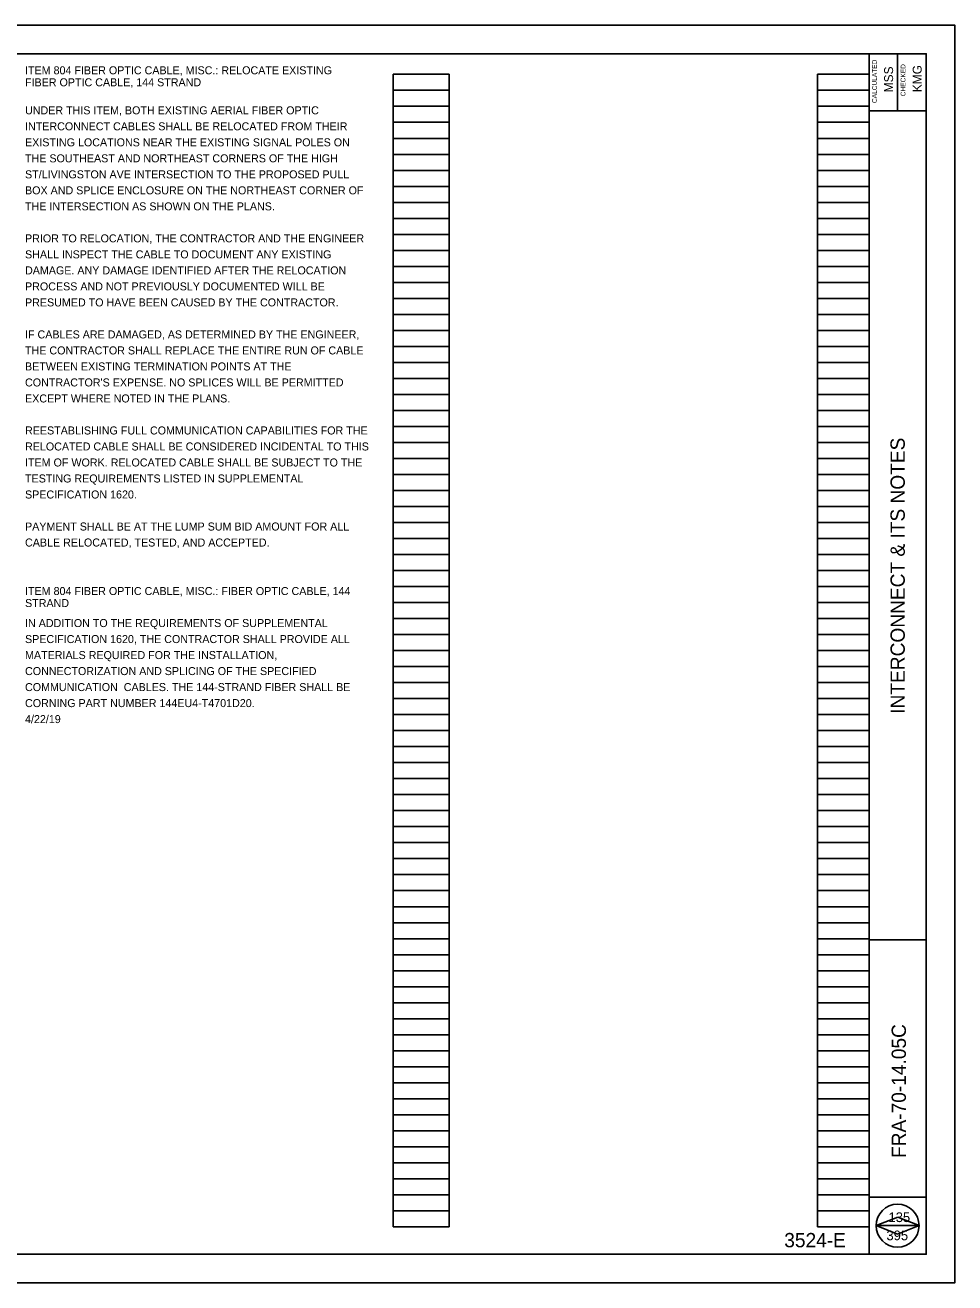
# Model space of a CAD drawing. Extents: x -39 to 75, y -25 to 14.
# Drawn here: x 17.24 to 33.49, y -7.51 to 14.49 of the extents above; entities that cross this region are included whole.
import ezdxf

# ---------------------------------------------------------------- set-up
doc = ezdxf.new("R2010")
doc.units = 0
for name, color, linetype in [('Level 63', 7, 'Continuous'), ('PF_P_Text', 7, 'Continuous'), ('SC_Scratch1', 7, 'Continuous'), ('SH_Cut_Line', 7, 'Continuous'), ('SH_Data', 7, 'Continuous'), ('SH_Text', 7, 'Continuous')]:
    doc.layers.add(name, color=color, linetype=linetype)

msp = doc.modelspace()

# ---------------------------------------------------------------- linework, layer by layer
at = {"layer": 'Level 63'}
msp.add_line((32.119, -6.508), (32.869, -6.508), dxfattribs=at)
msp.add_line((32.119, -6.508), (32.869, -6.508), dxfattribs=at)
msp.add_circle((32.494, -6.508), 0.375, dxfattribs=at)
at = {"layer": 'PF_P_Text'}
for p, q in [((31.994, -7.008), (31.994, 13.992)), ((32.494, 13.992), (32.494, 12.992)), ((31.994, 12.992), (32.994, 12.992)), ((31.994, -1.508), (32.994, -1.508)), ((31.994, -6.008), (32.994, -6.008))]:
    msp.add_line(p, q, dxfattribs=at)
msp.add_lwpolyline([(1.494, 13.992), (32.994, 13.992), (32.994, -7.008), (1.494, -7.008)], close=True, dxfattribs=at)
at = {"layer": 'SC_Scratch1'}
for p, q in [((23.674, -6.528), (23.674, 13.632)), ((23.674, 13.632), (24.654, 13.632)), ((24.654, -6.528), (24.654, 13.632)), ((31.094, -6.528), (31.094, 13.632)), ((31.094, 13.632), (31.994, 13.632)), ((31.994, -6.528), (31.994, 13.632)), ((23.674, 13.352), (24.654, 13.352)), ((31.094, 13.352), (31.994, 13.352)), ((23.674, 13.072), (24.654, 13.072)), ((31.094, 13.072), (31.994, 13.072)), ((23.674, 12.792), (24.654, 12.792)), ((31.094, 12.792), (31.994, 12.792)), ((23.674, 12.512), (24.654, 12.512)), ((31.094, 12.512), (31.994, 12.512)), ((23.674, 12.232), (24.654, 12.232)), ((31.094, 12.232), (31.994, 12.232)), ((23.674, 11.952), (24.654, 11.952)), ((31.094, 11.952), (31.994, 11.952)), ((23.674, 11.672), (24.654, 11.672)), ((31.094, 11.672), (31.994, 11.672)), ((23.674, 11.392), (24.654, 11.392)), ((31.094, 11.392), (31.994, 11.392)), ((23.674, 11.112), (24.654, 11.112)), ((31.094, 11.112), (31.994, 11.112)), ((23.674, 10.832), (24.654, 10.832)), ((31.094, 10.832), (31.994, 10.832)), ((23.674, 10.552), (24.654, 10.552)), ((31.094, 10.552), (31.994, 10.552)), ((23.674, 10.272), (24.654, 10.272)), ((31.094, 10.272), (31.994, 10.272)), ((23.674, 9.992), (24.654, 9.992)), ((31.094, 9.992), (31.994, 9.992)), ((23.674, 9.712), (24.654, 9.712)), ((31.094, 9.712), (31.994, 9.712)), ((23.674, 9.432), (24.654, 9.432)), ((31.094, 9.432), (31.994, 9.432)), ((23.674, 9.152), (24.654, 9.152)), ((31.094, 9.152), (31.994, 9.152)), ((23.674, 8.872), (24.654, 8.872)), ((31.094, 8.872), (31.994, 8.872)), ((23.674, 8.592), (24.654, 8.592)), ((31.094, 8.592), (31.994, 8.592)), ((23.674, 8.312), (24.654, 8.312)), ((31.094, 8.312), (31.994, 8.312)), ((23.674, 8.032), (24.654, 8.032)), ((31.094, 8.032), (31.994, 8.032)), ((23.674, 7.752), (24.654, 7.752)), ((31.094, 7.752), (31.994, 7.752)), ((23.674, 7.472), (24.654, 7.472)), ((31.094, 7.472), (31.994, 7.472)), ((23.674, 7.192), (24.654, 7.192)), ((31.094, 7.192), (31.994, 7.192)), ((23.674, 6.912), (24.654, 6.912)), ((31.094, 6.912), (31.994, 6.912)), ((23.674, 6.632), (24.654, 6.632)), ((31.094, 6.632), (31.994, 6.632)), ((23.674, 6.352), (24.654, 6.352)), ((31.094, 6.352), (31.994, 6.352)), ((23.674, 6.072), (24.654, 6.072)), ((31.094, 6.072), (31.994, 6.072)), ((23.674, 5.792), (24.654, 5.792)), ((31.094, 5.792), (31.994, 5.792)), ((23.674, 5.512), (24.654, 5.512)), ((31.094, 5.512), (31.994, 5.512)), ((23.674, 5.232), (24.654, 5.232)), ((31.094, 5.232), (31.994, 5.232)), ((23.674, 4.952), (24.654, 4.952)), ((31.094, 4.952), (31.994, 4.952)), ((23.674, 4.672), (24.654, 4.672)), ((31.094, 4.672), (31.994, 4.672)), ((23.674, 4.392), (24.654, 4.392)), ((31.094, 4.392), (31.994, 4.392)), ((23.674, 4.112), (24.654, 4.112)), ((31.094, 4.112), (31.994, 4.112)), ((23.674, 3.832), (24.654, 3.832)), ((31.094, 3.832), (31.994, 3.832)), ((23.674, 3.552), (24.654, 3.552)), ((31.094, 3.552), (31.994, 3.552)), ((23.674, 3.272), (24.654, 3.272)), ((31.094, 3.272), (31.994, 3.272)), ((23.674, 2.992), (24.654, 2.992)), ((31.094, 2.992), (31.994, 2.992)), ((23.674, 2.712), (24.654, 2.712)), ((31.094, 2.712), (31.994, 2.712)), ((23.674, 2.432), (24.654, 2.432)), ((31.094, 2.432), (31.994, 2.432)), ((23.674, 2.152), (24.654, 2.152)), ((31.094, 2.152), (31.994, 2.152)), ((23.674, 1.872), (24.654, 1.872)), ((31.094, 1.872), (31.994, 1.872)), ((23.674, 1.592), (24.654, 1.592)), ((31.094, 1.592), (31.994, 1.592)), ((23.674, 1.312), (24.654, 1.312)), ((31.094, 1.312), (31.994, 1.312)), ((23.674, 1.032), (24.654, 1.032)), ((31.094, 1.032), (31.994, 1.032)), ((23.674, 0.752), (24.654, 0.752)), ((31.094, 0.752), (31.994, 0.752)), ((23.674, 0.472), (24.654, 0.472)), ((31.094, 0.472), (31.994, 0.472)), ((23.674, 0.192), (24.654, 0.192)), ((31.094, 0.192), (31.994, 0.192)), ((23.674, -0.088), (24.654, -0.088)), ((31.094, -0.088), (31.994, -0.088)), ((23.674, -0.368), (24.654, -0.368)), ((31.094, -0.368), (31.994, -0.368)), ((23.674, -0.648), (24.654, -0.648)), ((31.094, -0.648), (31.994, -0.648)), ((23.674, -0.928), (24.654, -0.928)), ((31.094, -0.928), (31.994, -0.928)), ((23.674, -1.208), (24.654, -1.208)), ((31.094, -1.208), (31.994, -1.208)), ((23.674, -1.488), (24.654, -1.488)), ((31.094, -1.488), (31.994, -1.488)), ((23.674, -1.768), (24.654, -1.768)), ((31.094, -1.768), (31.994, -1.768)), ((23.674, -2.048), (24.654, -2.048)), ((31.094, -2.048), (31.994, -2.048)), ((23.674, -2.328), (24.654, -2.328)), ((31.094, -2.328), (31.994, -2.328)), ((23.674, -2.608), (24.654, -2.608)), ((31.094, -2.608), (31.994, -2.608)), ((23.674, -2.888), (24.654, -2.888)), ((31.094, -2.888), (31.994, -2.888)), ((23.674, -3.168), (24.654, -3.168)), ((31.094, -3.168), (31.994, -3.168)), ((23.674, -3.448), (24.654, -3.448)), ((31.094, -3.448), (31.994, -3.448)), ((23.674, -3.728), (24.654, -3.728)), ((31.094, -3.728), (31.994, -3.728)), ((23.674, -4.008), (24.654, -4.008)), ((31.094, -4.008), (31.994, -4.008)), ((23.674, -4.288), (24.654, -4.288)), ((31.094, -4.288), (31.994, -4.288)), ((23.674, -4.568), (24.654, -4.568)), ((31.094, -4.568), (31.994, -4.568)), ((23.674, -4.848), (24.654, -4.848)), ((31.094, -4.848), (31.994, -4.848)), ((23.674, -5.128), (24.654, -5.128)), ((31.094, -5.128), (31.994, -5.128)), ((23.674, -5.408), (24.654, -5.408)), ((31.094, -5.408), (31.994, -5.408)), ((23.674, -5.688), (24.654, -5.688)), ((31.094, -5.688), (31.994, -5.688)), ((23.674, -5.968), (24.654, -5.968)), ((31.094, -5.968), (31.994, -5.968)), ((23.674, -6.248), (24.654, -6.248)), ((31.094, -6.248), (31.994, -6.248)), ((32.119, -6.508), (32.495, -6.36)), ((32.495, -6.36), (32.869, -6.508)), ((23.674, -6.528), (24.654, -6.528)), ((31.094, -6.528), (31.994, -6.528)), ((32.49, -6.654), (32.119, -6.508)), ((32.869, -6.508), (32.49, -6.654))]:
    msp.add_line(p, q, dxfattribs=at)
at = {"layer": 'SH_Cut_Line'}
msp.add_lwpolyline([(-0.506, -7.508), (33.494, -7.508), (33.494, 14.492), (-0.506, 14.492)], close=True, dxfattribs=at)

# ---------------------------------------------------------------- texts
at = {"layer": 'Level 63'}
for s, p in [('CALCULATED', (32.13, 13.129)), ('CHECKED', (32.63, 13.248))]:
    msp.add_text(s, height=0.0833, rotation=90, dxfattribs=at).set_placement(p)
at = {"layer": 'SH_Data'}
for s, p in [('ITEM 804 FIBER OPTIC CABLE, MISC.: RELOCATE EXISTING ', (17.234, 13.632)), ('FIBER OPTIC CABLE, 144 STRAND ', (17.234, 13.422)), ('ITEM 804 FIBER OPTIC CABLE, MISC.: FIBER OPTIC CABLE, 144 ', (17.234, 4.523)), ('STRAND ', (17.234, 4.313))]:
    msp.add_text(s, height=0.14, dxfattribs=at).set_placement(p)
msp.add_text('3524-E', height=0.25, rotation=359.9999, dxfattribs=at).set_placement((30.511, -6.886))
at = {"layer": 'SH_Text'}
for s, height, rotation, p in [('MSS', 0.156, 90, (32.414, 13.317)), ('KMG', 0.156, 90, (32.914, 13.319)), ('UNDER THIS ITEM, BOTH EXISTING AERIAL FIBER OPTIC ', 0.14, 360, (17.234, 12.932)), ('INTERCONNECT CABLES SHALL BE RELOCATED FROM THEIR ', 0.14, 360, (17.234, 12.652)), ('EXISTING LOCATIONS NEAR THE EXISTING SIGNAL POLES ON ', 0.14, 360, (17.234, 12.372)), ('THE SOUTHEAST AND NORTHEAST CORNERS OF THE HIGH ', 0.14, 360, (17.234, 12.092)), ('ST/LIVINGSTON AVE INTERSECTION TO THE PROPOSED PULL ', 0.14, 360, (17.234, 11.812)), ('BOX AND SPLICE ENCLOSURE ON THE NORTHEAST CORNER OF ', 0.14, 360, (17.234, 11.532)), ('THE INTERSECTION AS SHOWN ON THE PLANS.', 0.14, 360, (17.234, 11.252)), ('PRIOR TO RELOCATION, THE CONTRACTOR AND THE ENGINEER ', 0.14, 360, (17.234, 10.692)), ('SHALL INSPECT THE CABLE TO DOCUMENT ANY EXISTING ', 0.14, 360, (17.234, 10.412)), ('DAMAGE. ANY DAMAGE IDENTIFIED AFTER THE RELOCATION ', 0.14, 360, (17.234, 10.132)), ('PROCESS AND NOT PREVIOUSLY DOCUMENTED WILL BE ', 0.14, 360, (17.234, 9.852)), ('PRESUMED TO HAVE BEEN CAUSED BY THE CONTRACTOR.', 0.14, 360, (17.234, 9.572)), ('IF CABLES ARE DAMAGED, AS DETERMINED BY THE ENGINEER, ', 0.14, 360, (17.234, 9.012)), ('THE CONTRACTOR SHALL REPLACE THE ENTIRE RUN OF CABLE ', 0.14, 360, (17.234, 8.732)), ('BETWEEN EXISTING TERMINATION POINTS AT THE ', 0.14, 360, (17.234, 8.452)), ("CONTRACTOR'S EXPENSE. NO SPLICES WILL BE PERMITTED ", 0.14, 360, (17.234, 8.172)), ('EXCEPT WHERE NOTED IN THE PLANS.', 0.14, 360, (17.234, 7.892)), ('REESTABLISHING FULL COMMUNICATION CAPABILITIES FOR THE ', 0.14, 360, (17.234, 7.332)), ('INTERCONNECT & ITS NOTES', 0.25, 90, (32.619, 2.447)), ('RELOCATED CABLE SHALL BE CONSIDERED INCIDENTAL TO THIS ', 0.14, 360, (17.234, 7.052)), ('ITEM OF WORK. RELOCATED CABLE SHALL BE SUBJECT TO THE ', 0.14, 360, (17.234, 6.772)), ('TESTING REQUIREMENTS LISTED IN SUPPLEMENTAL ', 0.14, 360, (17.234, 6.492)), ('SPECIFICATION 1620.', 0.14, 360, (17.234, 6.212)), ('PAYMENT SHALL BE AT THE LUMP SUM BID AMOUNT FOR ALL ', 0.14, 360, (17.234, 5.652)), ('CABLE RELOCATED, TESTED, AND ACCEPTED.', 0.14, 360, (17.234, 5.372)), ('IN ADDITION TO THE REQUIREMENTS OF SUPPLEMENTAL ', 0.14, 360, (17.234, 3.963)), ('SPECIFICATION 1620, THE CONTRACTOR SHALL PROVIDE ALL ', 0.14, 360, (17.234, 3.683)), ('MATERIALS REQUIRED FOR THE INSTALLATION, ', 0.14, 360, (17.234, 3.403)), ('CONNECTORIZATION AND SPLICING OF THE SPECIFIED ', 0.14, 360, (17.234, 3.123)), ('COMMUNICATION  CABLES. THE 144-STRAND FIBER SHALL BE ', 0.14, 360, (17.234, 2.843)), ('CORNING PART NUMBER 144EU4-T4701D20. ', 0.14, 360, (17.234, 2.563)), ('4/22/19', 0.14, 360, (17.234, 2.283)), ('FRA-70-14.05C', 0.25, 90, (32.639, -5.324))]:
    msp.add_text(s, height=height, rotation=rotation, dxfattribs=at).set_placement(p)
for s, p in [('135', (32.334, -6.445)), ('395', (32.298, -6.763))]:
    msp.add_text(s, height=0.17, dxfattribs=at).set_placement(p)

doc.saveas('drawing.dxf')
